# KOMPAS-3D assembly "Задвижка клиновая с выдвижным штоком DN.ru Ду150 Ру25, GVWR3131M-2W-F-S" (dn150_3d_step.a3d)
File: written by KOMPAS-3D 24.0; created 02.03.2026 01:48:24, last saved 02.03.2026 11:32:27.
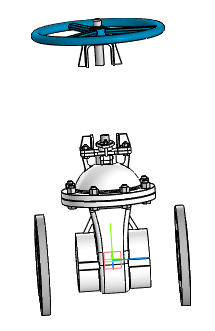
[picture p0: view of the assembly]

Document properties: Автор: R2D2; Полное имя файла: E:\Работа\Зайцев\GVWR3131M-2W-F-S Задвижка клиновая 30нж64нж DN.ru  Ду50-150 Ру25\исходные данные\DN150\dn150_3d_step.a3d

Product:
- Component [detail]: Деталь2  | qty 1  | pos. 1  | Масса: 6.212923; Автор: R2D2; additional columns: Типовые; source file: Деталь2 Деталь2.m3d
- Component [detail]: ANSI B18.2.4.2M - M16x2 - 24  | designation ANSI B18.2.4.2M - M16x2  | qty 8  | pos. 2  | Масса: 0.044671; Комментарий: Типы метрических   шестигранных гаек   2; Автор: R2D2; additional columns: Сталь, мягкая; source file: ANSI B18.2.4.2M - M16x2 ANSI B18.2.4.2M - M16x2 - 24.m3d
- Component [detail]: AS 1110 - M16 x 60  | qty 8  | pos. 3  | Масса: 0.133772; Комментарий: Болты и винты   шестигранные точные   метрические ISO; Автор: R2D2; additional columns: Сталь, мягкая; source file: AS 1110 - M16 x 60 AS 1110 - M16 x 60.m3d
- Component [detail]: AS 1110 - M10 x 35  | qty 4  | pos. 4  | Масса: 0.032708; Комментарий: Болты и винты   шестигранные точные   метрические ISO; Автор: R2D2; additional columns: Сталь, мягкая; source file: AS 1110 - M10 x 35 AS 1110 - M10 x 35.m3d
- Component [detail]: ANSI B18.2.4.2M - M10x1,5 - 16  | designation ANSI B18.2.4.2M - M10x1,5  | qty 4  | pos. 5  | Масса: 0.012122; Комментарий: Типы метрических   шестигранных гаек   2; Автор: R2D2; additional columns: Сталь, мягкая; source file: ANSI B18.2.4.2M - M10x1,5 ANSI B18.2.4.2M - M10x1,5 - 16.m3d
- Component [detail]: ANSI B18.2.4.2M - M8x1,25 - 13  | designation ANSI B18.2.4.2M - M8x1,25  | qty 1  | pos. 6  | Масса: 0.006562; Комментарий: Типы метрических   шестигранных гаек   2; Автор: R2D2; additional columns: Сталь, мягкая; source file: ANSI B18.2.4.2M - M8x1,25 ANSI B18.2.4.2M - M8x1,25 - 13.m3d
- Component [detail]: Деталь1  | qty 1  | pos. 7  | Масса: 76.825257; Автор: R2D2; additional columns: Типовые; source file: 2.m3d
- Component [detail]: Деталь1  | qty 1  | pos. 7  | Масса: 1.47915; Автор: R2D2; additional columns: Типовые; source file: 3.m3d
- Component [detail]: Деталь1  | qty 2  | Масса: 10.128397; Автор: R2D2; additional columns: Типовые; source file: 1.m3d
- Component [detail]: ANSI B18.2.4.2M - M8x1,25 - 13  | designation ANSI B18.2.4.2M - M8x1,25-01  | qty 1  | pos. 6  | Масса: 0.006562; Комментарий: Типы метрических   шестигранных гаек   2; Автор: R2D2; additional columns: Сталь, мягкая; source file: ANSI B18.2.4.2M - M8x1,25 ANSI B18.2.4.2M - M8x1,25 - 13.m3d
- Part/product: Задвижка клиновая с выдвижным штоком DN.ru Ду150 Ру25  | designation GVWR3131M-2W-F-S
    Масса: 61
    Раздел спецификации: Прочие изделия
    Примечание: D040-07877

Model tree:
1. Массив по сетке:2  (labels: Грань.Твердое тело1; Вершина.Твердое тело1)  (4 pattern instances)
     Шаг 1 = 50; Угол раствора = 90; Шаг 2 = 120
2. Массив по концентрической сетке:1  (with: Грань.Элемент вращения:1)  (labels: Грань.Твердое тело1; Грань.Solid1)  (8 pattern instances)
     Шаг 2 = 360; Расстояние = -727.5; Расстояние = -225; Ориентация = 2; Ориентация = 2

Referenced files in E:\Работа\Зайцев\GVWR3131M-2W-F-S Задвижка клиновая 30нж64нж DN.ru  Ду50-150 Ру25\исходные данные\DN150\: Деталь2 Деталь2.m3d, ANSI B18.2.4.2M - M16x2 ANSI B18.2.4.2M - M16x2 - 24.m3d, AS 1110 - M16 x 60 AS 1110 - M16 x 60.m3d, AS 1110 - M10 x 35 AS 1110 - M10 x 35.m3d, ANSI B18.2.4.2M - M10x1,5 ANSI B18.2.4.2M - M10x1,5 - 16.m3d, ANSI B18.2.4.2M - M8x1,25 ANSI B18.2.4.2M - M8x1,25 - 13.m3d, 2.m3d, 1.m3d, 3.m3d
Referenced files in E:\Работа\Зайцев\GVWR3131M-2W-F-S Задвижка клиновая с выдвижным штоком DN.ru Ду50-200 Ру63\DN150\исходные материалы\: 1.m3d, ANSI B18.2.4.2M - M10x1,5 ANSI B18.2.4.2M - M10x1,5 - 16.m3d, AS 1110 - M10 x 35 AS 1110 - M10 x 35.m3d, ANSI B18.2.4.2M - M16x2 ANSI B18.2.4.2M - M16x2 - 24.m3d, AS 1110 - M16 x 60 AS 1110 - M16 x 60.m3d
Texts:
  Программные изделия  и базы данных
  ANSI B18.2.4.2M - M16x2
  ANSI B18.2.4.2M - M10x1,5
  ANSI B18.2.4.2M - M8x1,25
  ANSI B18.2.4.2M - M8x1,25 - 01
  ANSI B18.2.4.2M - M8x1,25-01
  GVWR3131M-2W-F-S
  Деталь2 Деталь2
  ANSI B18.2.4.2M - M16x2 ANSI B18.2.4.2M - M16x2 - 24 (1)
  AS 1110 - M16 x 60 AS 1110 - M16 x 60 (1)
  AS 1110 - M10 x 35 AS 1110 - M10 x 35 (1)
  ANSI B18.2.4.2M - M10x1,5 ANSI B18.2.4.2M - M10x1,5 - 16 (1)
  ANSI B18.2.4.2M - M8x1,25 ANSI B18.2.4.2M - M8x1,25 - 13
  Деталь1 Деталь1
  Деталь1 Деталь1 (1)
  Деталь1 Деталь1 (2)
  ANSI B18.2.4.2M - M8x1,25-01 ANSI B18.2.4.2M - M8x1,25 - 13
  Ось Z.Начало координат
  Ось Y.Начало координат
  Плоскость ZX.Начало координат
  Плоскость ZY.Начало координат
  Плоскость XY.Начало координат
